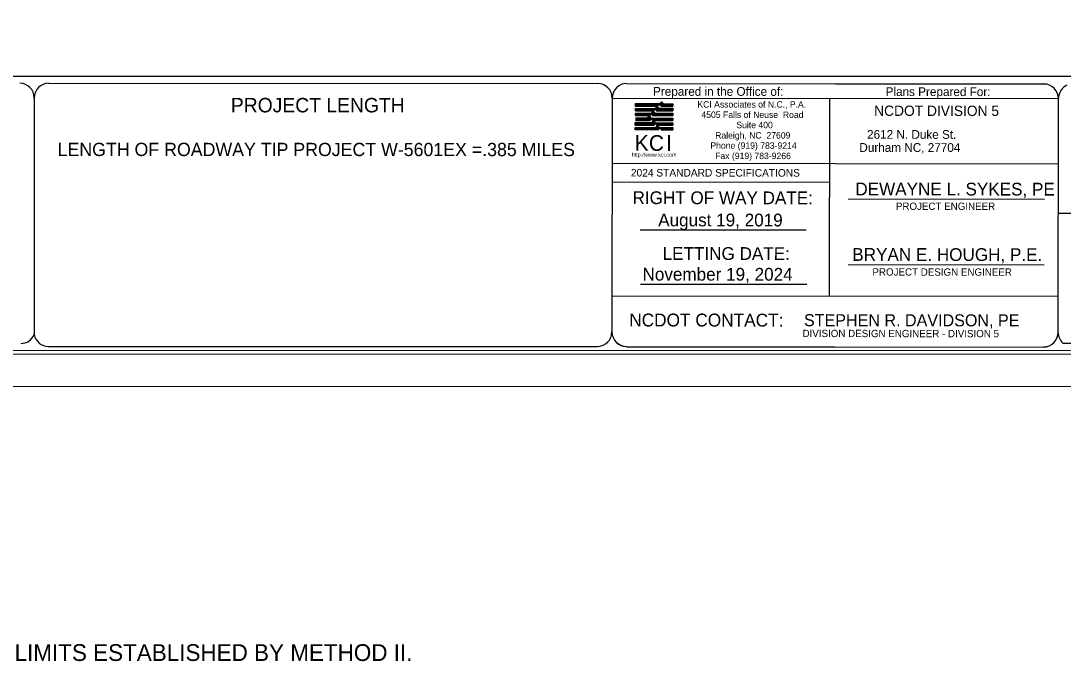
# Model space of a CAD drawing. Extents: x 2110629 to 2114002, y 669321 to 671542.
# Drawn here: x 2111580 to 2112822, y 669321 to 670084 of the extents above; entities that cross this region are included whole.
import ezdxf

# ---------------------------------------------------------------- set-up
doc = ezdxf.new("R2010")
doc.units = 0
for name, color, linetype in [('Default Symbol Cogo Number', 7, 'Continuous'), ('Exist Guardrail', 7, 'Continuous'), ('Exist Other Culture Anchor (Guy Wire) CELL', 7, 'Continuous'), ('Exist Roads Curbs', 7, 'Continuous'), ('Exist Roads EOP Other Text', 7, 'Continuous'), ('Exist Structure Minor Catch Basin', 7, 'Continuous'), ('Exist Utilities Telephone Test Hole SUE LOS A Text', 7, 'Continuous'), ('Exist Utilities Water Test Hole SUE LOS A Text', 7, 'Continuous')]:
    doc.layers.add(name, color=color, linetype=linetype)

msp = doc.modelspace()

# ---------------------------------------------------------------- linework, layer by layer
at = {"layer": 'Default Symbol Cogo Number'}
for p, q in [((2112312.6, 669985.6), (2112345.6, 669985.6)), ((2112312.6, 669985.4), (2112357.3, 669985.4)), ((2112312.6, 669985.2), (2112357.3, 669985.1)), ((2112312.6, 669984.9), (2112357.3, 669984.9)), ((2112312.6, 669984.7), (2112341.1, 669984.7)), ((2112312.6, 669984.5), (2112340.9, 669984.4)), ((2112312.6, 669984.2), (2112340.6, 669984.2)), ((2112312.6, 669984), (2112340.4, 669983.9)), ((2112312.6, 669983.7), (2112340.2, 669983.7)), ((2112312.6, 669983.5), (2112339.9, 669983.5)), ((2112312.6, 669983.3), (2112339.7, 669983.2)), ((2112312.6, 669983), (2112339.5, 669983)), ((2112312.6, 669982.8), (2112339.2, 669982.7)), ((2112312.6, 669979.9), (2112357.3, 669979.9)), ((2112312.6, 669979.7), (2112357.3, 669979.6)), ((2112312.6, 669979.4), (2112357.3, 669979.4)), ((2112312.6, 669979.2), (2112357.3, 669979.1)), ((2112312.6, 669978.9), (2112336.1, 669978.9)), ((2112312.6, 669978.7), (2112335.8, 669978.7)), ((2112312.6, 669978.5), (2112335.6, 669978.4)), ((2112312.6, 669978.2), (2112335.3, 669978.2)), ((2112312.6, 669978), (2112335.1, 669978)), ((2112312.6, 669977.7), (2112334.8, 669977.7)), ((2112312.6, 669977.5), (2112334.5, 669977.5)), ((2112312.6, 669977.3), (2112334.3, 669977.2)), ((2112332.6, 669975.4), (2112335, 669975.4)), ((2112332.8, 669975.6), (2112334.8, 669975.6)), ((2112333, 669975.8), (2112334.6, 669975.8)), ((2112333.3, 669976.1), (2112334.4, 669976.1)), ((2112333.5, 669976.3), (2112334.2, 669976.3)), ((2112333.7, 669976.6), (2112334, 669976.6)), ((2112336.2, 669978.9), (2112357.3, 669978.9)), ((2112336.4, 669978.7), (2112357.3, 669978.7)), ((2112336.7, 669978.4), (2112357.3, 669978.4)), ((2112336.9, 669980.1), (2112357.3, 669980.1)), ((2112336.9, 669978.2), (2112357.3, 669978.2)), ((2112337.1, 669980.4), (2112340.6, 669980.4)), ((2112337.2, 669978), (2112357.3, 669977.9)), ((2112337.3, 669980.6), (2112340.4, 669980.6)), ((2112337.4, 669977.7), (2112357.3, 669977.7)), ((2112337.5, 669980.8), (2112340.1, 669980.8)), ((2112337.6, 669977.5), (2112357.3, 669977.4)), ((2112337.7, 669981.1), (2112339.9, 669981.1)), ((2112337.9, 669981.3), (2112339.6, 669981.3)), ((2112337.9, 669977.2), (2112357.3, 669977.2)), ((2112338.1, 669981.5), (2112339.4, 669981.5)), ((2112338.4, 669981.8), (2112339.1, 669981.8)), ((2112338.6, 669982), (2112338.9, 669982)), ((2112341.4, 669984.7), (2112357.3, 669984.6)), ((2112341.6, 669984.4), (2112357.3, 669984.4)), ((2112341.8, 669984.2), (2112357.3, 669984.2)), ((2112342, 669985.9), (2112345.4, 669985.9)), ((2112342.1, 669983.9), (2112357.3, 669983.9)), ((2112342.2, 669986.1), (2112345.2, 669986.1)), ((2112342.3, 669983.7), (2112357.3, 669983.7)), ((2112342.4, 669986.3), (2112345, 669986.3)), ((2112342.5, 669983.5), (2112357.3, 669983.4)), ((2112342.6, 669986.6), (2112344.8, 669986.6)), ((2112342.8, 669983.2), (2112357.3, 669983.2)), ((2112342.9, 669986.8), (2112344.6, 669986.8)), ((2112343, 669983), (2112357.3, 669983)), ((2112343.1, 669987.1), (2112344.4, 669987.1)), ((2112343.2, 669982.7), (2112357.3, 669982.7)), ((2112343.3, 669987.3), (2112344.2, 669987.3)), ((2112343.5, 669987.5), (2112344, 669987.5)), ((2112312.6, 669974.2), (2112357.3, 669974.1)), ((2112312.6, 669973.9), (2112357.3, 669973.9)), ((2112312.6, 669973.7), (2112357.3, 669973.7)), ((2112312.6, 669973.5), (2112331, 669973.5)), ((2112312.6, 669973.2), (2112330.8, 669973.2)), ((2112312.6, 669973), (2112330.6, 669973)), ((2112312.6, 669972.8), (2112330.4, 669972.7)), ((2112312.6, 669972.5), (2112330.2, 669972.5)), ((2112312.6, 669972.3), (2112330, 669972.3)), ((2112312.6, 669972), (2112329.8, 669972)), ((2112312.6, 669971.8), (2112329.6, 669971.8)), ((2112312.6, 669971.6), (2112329.3, 669971.5)), ((2112312.6, 669968.6), (2112327.2, 669968.6)), ((2112312.6, 669968.3), (2112357.3, 669968.3)), ((2112312.6, 669968.1), (2112357.3, 669968.1)), ((2112312.6, 669967.9), (2112331.7, 669967.8)), ((2112312.6, 669967.6), (2112331.4, 669967.6)), ((2112312.6, 669967.4), (2112331.2, 669967.4)), ((2112312.6, 669967.1), (2112331, 669967.1)), ((2112312.6, 669966.9), (2112330.8, 669966.9)), ((2112312.6, 669966.7), (2112330.6, 669966.6)), ((2112312.6, 669966.4), (2112330.4, 669966.4)), ((2112312.6, 669966.2), (2112330.2, 669966.2)), ((2112312.6, 669965.9), (2112330, 669965.9)), ((2112312.6, 669965.7), (2112329.8, 669965.7)), ((2112329.7, 669965.6), (2112312.6, 669965.6)), ((2112312.5, 669963), (2112336.1, 669963)), ((2112326.6, 669974.4), (2112357.3, 669974.4)), ((2112327.2, 669968.6), (2112329.1, 669971)), ((2112327.2, 669968.6), (2112331.3, 669968.6)), ((2112327.4, 669968.8), (2112331.1, 669968.8)), ((2112327.6, 669969.1), (2112330.9, 669969)), ((2112327.8, 669969.3), (2112330.7, 669969.3)), ((2112327.9, 669969.5), (2112330.4, 669969.5)), ((2112328.1, 669969.8), (2112330.2, 669969.8)), ((2112328.3, 669970), (2112330, 669970)), ((2112328.5, 669970.2), (2112329.8, 669970.2)), ((2112328.7, 669970.5), (2112329.6, 669970.5)), ((2112328.9, 669970.7), (2112329.4, 669970.7)), ((2112329.1, 669971), (2112329.2, 669971)), ((2112329.1, 669971), (2112331.3, 669968.5)), ((2112331.7, 669967.8), (2112329.7, 669965.6)), ((2112331.3, 669973.5), (2112357.3, 669973.4)), ((2112331.3, 669968.5), (2112357.3, 669968.5)), ((2112331.5, 669973.2), (2112357.3, 669973.2)), ((2112331.7, 669973), (2112357.3, 669972.9)), ((2112331.7, 669967.8), (2112357.3, 669967.8)), ((2112333.9, 669965.7), (2112331.7, 669967.8)), ((2112331.8, 669974.7), (2112335.6, 669974.6)), ((2112331.9, 669967.6), (2112357.3, 669967.6)), ((2112332, 669972.7), (2112357.3, 669972.7)), ((2112332.1, 669974.9), (2112335.4, 669974.9)), ((2112332.2, 669972.5), (2112357.3, 669972.5)), ((2112332.2, 669967.4), (2112357.3, 669967.3)), ((2112332.3, 669975.1), (2112335.2, 669975.1)), ((2112332.4, 669972.2), (2112357.3, 669972.2)), ((2112332.4, 669967.1), (2112357.3, 669967.1)), ((2112332.5, 669963.2), (2112335.9, 669963.2)), ((2112332.6, 669972), (2112357.3, 669972)), ((2112332.6, 669966.9), (2112357.3, 669966.8)), ((2112332.7, 669963.5), (2112335.7, 669963.5)), ((2112332.8, 669971.8), (2112357.3, 669971.7)), ((2112332.9, 669966.6), (2112357.3, 669966.6)), ((2112332.9, 669963.7), (2112335.6, 669963.7)), ((2112333, 669971.5), (2112357.3, 669971.5)), ((2112333.1, 669966.4), (2112357.3, 669966.4)), ((2112333.1, 669964), (2112335.4, 669964)), ((2112333.3, 669964.2), (2112335.2, 669964.2)), ((2112333.4, 669966.2), (2112357.3, 669966.1)), ((2112333.5, 669964.5), (2112335, 669964.5)), ((2112333.6, 669965.9), (2112357.3, 669965.9)), ((2112333.7, 669964.7), (2112334.8, 669964.7)), ((2112333.9, 669965.7), (2112357.3, 669965.7)), ((2112357.3, 669965.6), (2112333.9, 669965.7)), ((2112333.9, 669964.9), (2112334.6, 669964.9)), ((2112334.1, 669965.2), (2112334.4, 669965.2)), ((2112357.3, 669968.5), (2112357.3, 669965.6)), ((2112312.5, 669962.1), (2112336.6, 669962.1)), ((2112312.5, 669961.8), (2112336.4, 669961.8)), ((2112312.5, 669961.6), (2112336.2, 669961.6)), ((2112312.5, 669961.4), (2112336, 669961.3)), ((2112312.5, 669961.1), (2112335.8, 669961.1)), ((2112312.5, 669960.9), (2112335.6, 669960.9)), ((2112312.5, 669960.6), (2112335.4, 669960.6)), ((2112312.5, 669960.4), (2112335.2, 669960.4)), ((2112312.5, 669960.2), (2112334.9, 669960.1)), ((2112312.5, 669957.3), (2112357.3, 669957.2)), ((2112312.5, 669957), (2112357.3, 669957)), ((2112312.5, 669956.8), (2112357.3, 669956.8)), ((2112312.5, 669956.6), (2112341.8, 669956.5)), ((2112312.5, 669956.3), (2112341.6, 669956.3)), ((2112312.5, 669956.1), (2112341.3, 669956.1)), ((2112312.5, 669955.8), (2112341.1, 669955.8)), ((2112312.5, 669955.6), (2112340.9, 669955.6)), ((2112312.5, 669955.4), (2112340.7, 669955.3)), ((2112312.5, 669955.1), (2112340.4, 669955.1)), ((2112312.5, 669954.9), (2112340.2, 669954.9)), ((2112312.5, 669954.7), (2112340, 669954.6)), ((2112312.5, 669962.8), (2112357.3, 669962.8)), ((2112312.5, 669962.6), (2112357.3, 669962.5)), ((2112312.5, 669962.3), (2112336.8, 669962.3)), ((2112336.9, 669962.3), (2112357.3, 669962.3)), ((2112337.1, 669962.1), (2112357.3, 669962)), ((2112337.2, 669957.5), (2112341, 669957.5)), ((2112337.3, 669961.8), (2112357.3, 669961.8)), ((2112337.4, 669961.6), (2112357.3, 669961.6)), ((2112337.4, 669957.7), (2112340.8, 669957.7)), ((2112337.6, 669961.3), (2112357.3, 669961.3)), ((2112337.6, 669958), (2112340.6, 669958)), ((2112337.8, 669961.1), (2112357.3, 669961.1)), ((2112337.9, 669960.9), (2112357.3, 669960.8)), ((2112337.9, 669958.2), (2112340.4, 669958.2)), ((2112338.1, 669960.6), (2112357.3, 669960.6)), ((2112338.1, 669958.4), (2112340.1, 669958.4)), ((2112338.3, 669960.4), (2112357.3, 669960.3)), ((2112338.3, 669958.7), (2112339.9, 669958.7)), ((2112338.5, 669960.1), (2112357.3, 669960.1)), ((2112338.5, 669958.9), (2112339.7, 669958.9)), ((2112338.8, 669959.2), (2112339.5, 669959.2)), ((2112339, 669959.4), (2112339.2, 669959.4)), ((2112341.8, 669956.5), (2112357.3, 669956.5)), ((2112342, 669956.3), (2112357.3, 669956.3)), ((2112342.3, 669956.1), (2112357.3, 669956)), ((2112342.5, 669955.8), (2112357.3, 669955.8)), ((2112342.7, 669955.6), (2112357.3, 669955.6)), ((2112342.9, 669955.3), (2112357.3, 669955.3)), ((2112343.1, 669955.1), (2112357.3, 669955.1)), ((2112343.3, 669954.9), (2112357.3, 669954.8)), ((2112343.5, 669954.6), (2112357.3, 669954.6)), ((2112343.7, 669954.4), (2112357.3, 669954.4))]:
    msp.add_line(p, q, dxfattribs=at)
for points in [[(2112312.6, 669985.7), (2112341.8, 669985.7), (2112343.8, 669987.8), (2112345.7, 669985.5), (2112357.3, 669985.5), (2112357.3, 669982.6), (2112343.3, 669982.6), (2112341.3, 669984.8), (2112339.1, 669982.7), (2112312.6, 669982.7)], [(2112312.6, 669980), (2112336.8, 669980), (2112338.7, 669982.2), (2112340.8, 669980.2), (2112357.3, 669980.2), (2112357.3, 669977.1), (2112338, 669977.1), (2112336.1, 669979), (2112334.1, 669977.1), (2112312.6, 669977.1)], [(2112312.6, 669974.4), (2112331.6, 669974.4), (2112333.9, 669976.7), (2112335.8, 669974.4), (2112357.3, 669974.4), (2112357.3, 669971.4), (2112333.1, 669971.4), (2112331.2, 669973.6), (2112329.3, 669971.4), (2112312.6, 669971.5)], [(2112312.5, 669963.1), (2112332.3, 669963), (2112334.3, 669965.4), (2112336.2, 669962.9), (2112357.3, 669962.8), (2112357.3, 669959.9), (2112338.6, 669960), (2112336.9, 669962.3), (2112334.8, 669960), (2112312.5, 669960)], [(2112312.5, 669957.4), (2112337, 669957.3), (2112339.1, 669959.5), (2112341.2, 669957.3), (2112357.3, 669957.3), (2112357.3, 669954.3), (2112343.8, 669954.3), (2112341.8, 669956.6), (2112339.7, 669954.4), (2112312.5, 669954.4)]]:
    msp.add_lwpolyline(points, close=True, dxfattribs=at)
at = {"layer": 'Exist Roads Curbs'}
msp.add_line((2110628.9, 669648.7), (2113527.5, 669648.2), dxfattribs=at)
at = {"layer": 'Exist Roads EOP Other Text'}
msp.add_lwpolyline([(2110651.3, 669687.3), (2113519.8, 669686.8), (2113520.1, 671502.9), (2110651.6, 671503.4)], close=True, dxfattribs=at)
at = {"layer": 'Exist Structure Minor Catch Basin'}
for p, q in [((2111028.3, 670018.7), (2113472.5, 670018.3)), ((2111613.5, 670010), (2112267.6, 670009.8)), ((2112302.5, 670009.7), (2112799.2, 670009.2)), ((2112302.5, 670009.6), (2112799.2, 670009.1)), ((2111596.3, 669992.8), (2111596.3, 669710.2)), ((2112285, 669992.3), (2112284.7, 669713.4)), ((2112285, 669992.3), (2112816, 669991.7)), ((2112544, 669992), (2112543.7, 669756.3)), ((2112816.4, 669712.8), (2112816.7, 669991.7)), ((2112815.9, 669913.7), (2112284.9, 669914.3)), ((2112816.6, 669913.7), (2112284.9, 669914.3)), ((2112514.2, 669891.8), (2112284.9, 669892.1)), ((2112543.9, 669891.8), (2112284.9, 669892.1)), ((2112447.9, 669891.9), (2112447.9, 669891.9)), ((2112448.1, 669891.9), (2112448.1, 669891.9)), ((2112448.1, 669891.8), (2112448.1, 669891.8)), ((2112566.2, 669872.1), (2112800, 669871.8)), ((2112816.5, 669854.9), (2113188.1, 669854.8)), ((2112404.4, 669840.4), (2112404.4, 669840.4)), ((2112516.3, 669834.6), (2112318.3, 669834.8)), ((2112404.5, 669808.5), (2112404.5, 669808.5)), ((2112566.2, 669793.8), (2112799.9, 669793.5)), ((2112517, 669769.8), (2112318.9, 669770.1)), ((2112284.8, 669756.5), (2112815.7, 669756))]:
    msp.add_line(p, q, dxfattribs=at)
for points in [[(2110933.6, 669691.6), (2113481, 669691.2)], [(2111613.2, 669696.2), (2112267.3, 669696.1)], [(2112302.1, 669696), (2112798.9, 669695.4)], [(2112302.1, 669695.8), (2112798.9, 669695.3)], [(2112822.1, 669699.9), (2113170.8, 669699.9)]]:
    msp.add_lwpolyline(points, dxfattribs=at)
for centre, radius, start, end in [((2111579.1, 669992.8), 17.2, 359.9903, 89.9903), ((2111613.5, 669992.8), 17.2, 89.9903, 179.9903), ((2112267.6, 669992.4), 17.4, 359.9376, 89.9376), ((2112267.6, 669992.3), 17.4, 359.9376, 89.9376), ((2112302.5, 669992.4), 17.4, 89.9376, 179.9376), ((2112302.5, 669992.3), 17.4, 89.9376, 179.9376), ((2112799.2, 669991.8), 17.4, 359.9376, 89.9376), ((2112799.2, 669991.7), 17.4, 359.9376, 89.9376), ((2112834.1, 669991.8), 17.4, 114.7561, 179.9376), ((2111580.4, 669716.9), 17.2, 269.9903, 337.3692), ((2111613.2, 669713.4), 17.2, 190.4989, 269.9903), ((2112267.3, 669713.5), 17.4, 269.9376, 359.9376), ((2112302.1, 669713.5), 17.4, 179.9376, 269.9376), ((2112302.1, 669713.4), 17.4, 179.9376, 269.9376), ((2112798.9, 669712.9), 17.4, 269.9376, 359.9376), ((2112798.9, 669712.8), 17.4, 269.9376, 359.9376), ((2112833.8, 669712.9), 17.4, 179.9376, 228.004)]:
    msp.add_arc(centre, radius, start, end, dxfattribs=at)
at = {"layer": 'Exist Utilities Water Test Hole SUE LOS A Text'}
msp.add_lwpolyline([(2113527.8, 671541.5), (2110629.2, 671542), (2110628.9, 669648.7), (2113527.5, 669648.2)], close=True, dxfattribs=at)

# ---------------------------------------------------------------- texts
at = {"layer": 'Default Symbol Cogo Number'}
for s, height, p in [('KCI Associates of N.C., P.A.', 7.681, (2112386.5, 669981)), ('4505 Falls of Neuse  Road ', 7.681, (2112391.3, 669968.7)), (' Suite 400', 7.68, (2112430.1, 669956.4)), ('Raleigh, NC  27609', 7.681, (2112407.7, 669944.1)), ('K', 18.7, (2112311.8, 669929.5)), ('C', 18.7, (2112328.7, 669929.4)), ('I', 18.7, (2112349.2, 669929.4)), ('Phone (919) 783-9214', 7.681, (2112402, 669931.9)), ('http://www.kci.com', 4.631, (2112308.3, 669922.5)), ('Fax (919) 783-9266', 7.681, (2112407.7, 669919.6))]:
    msp.add_text(s, height=height, rotation=359.9376, dxfattribs=at).set_placement(p)
at = {"layer": 'Exist Guardrail'}
msp.add_text('2. CLEARING ON THIS PROJECT SHALL BE PERFORMED TO THE LIMITS ESTABLISHED BY METHOD II.', height=20, dxfattribs=at).set_placement((2110731.8, 669321))
at = {"layer": 'Exist Other Culture Anchor (Guy Wire) CELL'}
msp.add_text('LENGTH OF ROADWAY TIP PROJECT W-5601EX =.385 MILES', height=15.816, rotation=359.9872, dxfattribs=at).set_placement((2111624.2, 669923.2))
at = {"layer": 'Exist Structure Minor Catch Basin'}
for s, height, rotation, p in [('Prepared in the Office of:', 10.444, 359.9376, (2112333.7, 669995.1)), ('Plans Prepared For:', 10.444, 359.9376, (2112610.8, 669994.8)), ('PROJECT LENGTH', 17.212, 359.9903, (2111830.6, 669975.3)), ('NCDOT DIVISION 5', 12.289, 359.9376, (2112597.1, 669971.1)), ('2612 N. Duke St.', 10.445, 359.9376, (2112588.7, 669943.8)), ('Durham NC, 27704', 10.445, 359.9376, (2112579.5, 669928.2)), ('2024 STANDARD SPECIFICATIONS', 9.064, 359.9376, (2112307.3, 669898.8)), ('RIGHT OF WAY DATE: ', 15.233, 359.9376, (2112309.2, 669865.9)), ('PROJECT ENGINEER', 8.704, 359.9376, (2112623, 669859)), ('LETTING DATE:', 15.233, 359.9376, (2112345.1, 669799.4)), ('PROJECT DESIGN ENGINEER', 8.704, 359.9376, (2112595.1, 669780.6)), ('DIVISION DESIGN ENGINEER - DIVISION 5', 8.704, 359.9376, (2112511.8, 669707.3))]:
    msp.add_text(s, height=height, rotation=rotation, dxfattribs=at).set_placement(p)
at = {"layer": 'Exist Utilities Telephone Test Hole SUE LOS A Text'}
for s, height, p in [('DEWAYNE L. SYKES, PE', 15.233, (2112574.7, 669876.3)), ('August 19, 2019', 15.233, (2112339.8, 669839.4)), ('BRYAN E. HOUGH, P.E.', 15.233, (2112571.1, 669798.2)), ('November 19, 2024', 15.233, (2112321.1, 669774.7)), ('NCDOT CONTACT:', 15.361, (2112305.3, 669720)), ('STEPHEN R. DAVIDSON, PE', 14.337, (2112513.5, 669720.3))]:
    msp.add_text(s, height=height, rotation=359.9376, dxfattribs=at).set_placement(p)

doc.saveas('drawing.dxf')
